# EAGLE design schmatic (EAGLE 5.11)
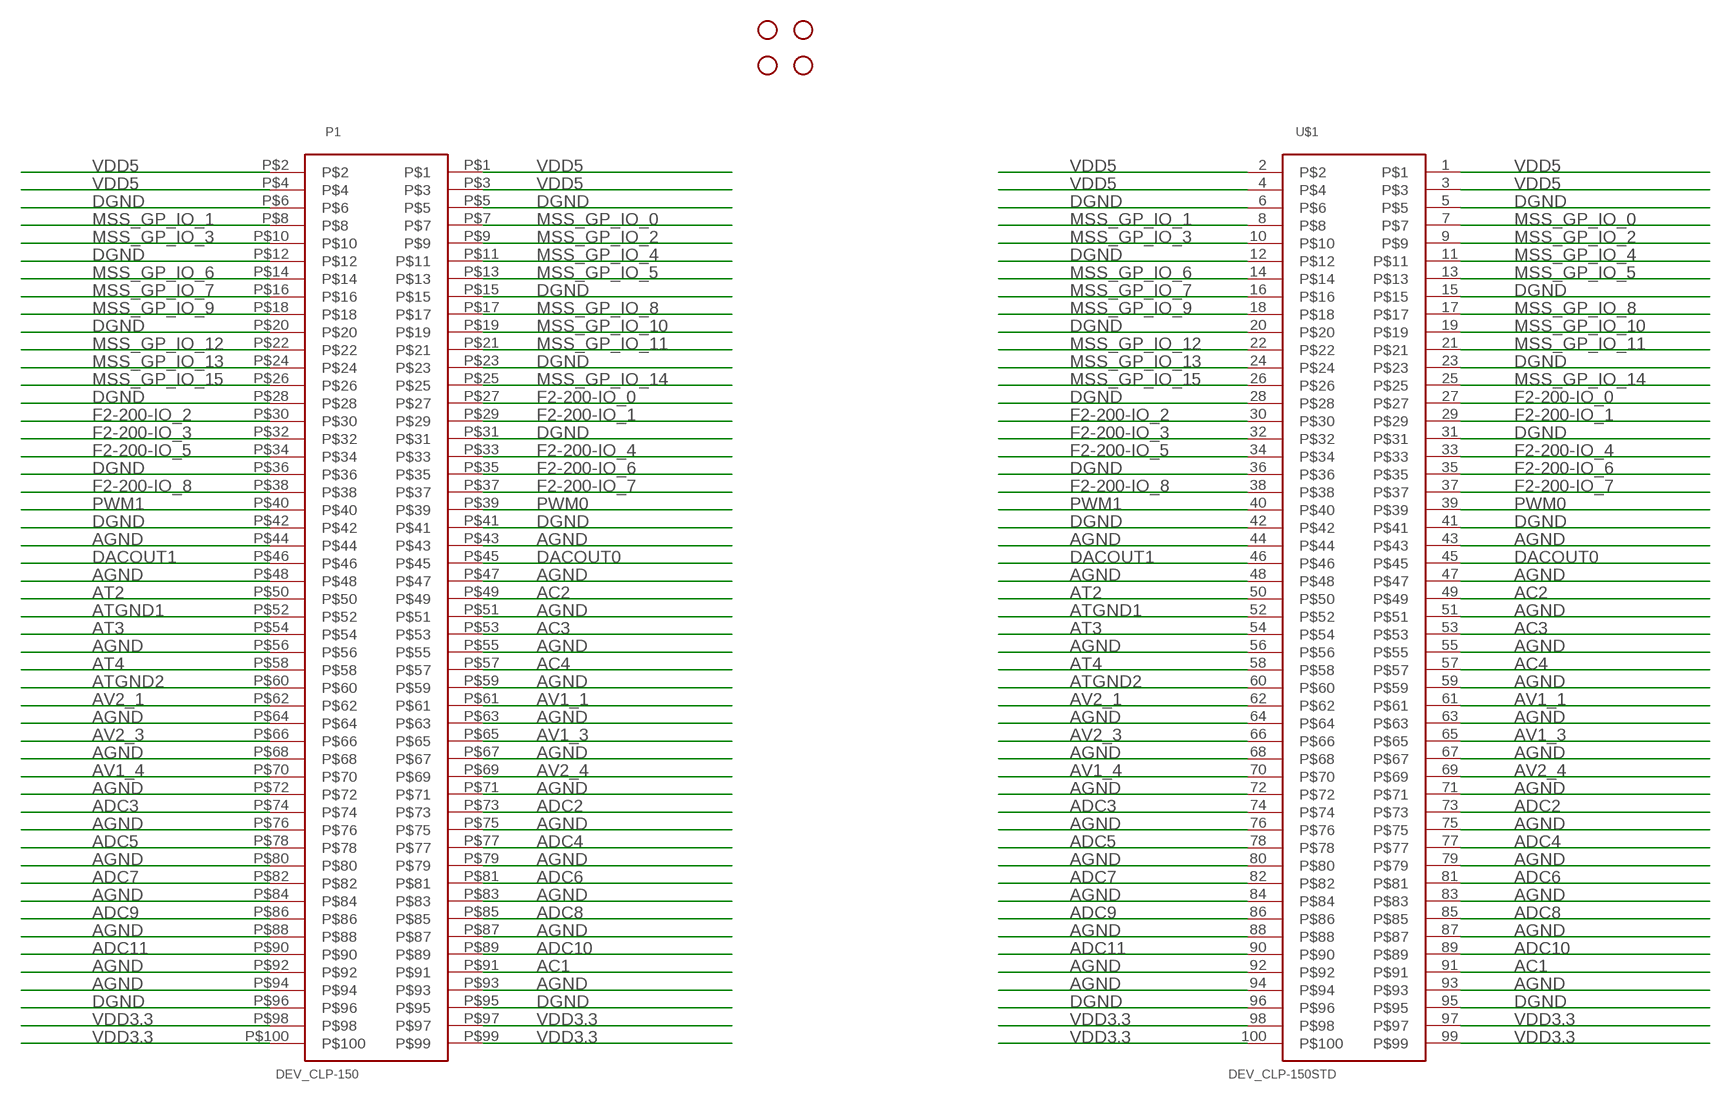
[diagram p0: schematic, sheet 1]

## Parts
JP1  STAND-OFF  [STAND-OFF]
JP2  STAND-OFF  [STAND-OFF]
JP3  STAND-OFF  [STAND-OFF]
JP4  STAND-OFF  [STAND-OFF]
P1  DEV_CLP-150  [CLP-150]
U$1  DEV_CLP-150STD  [100PIN_HEADER]

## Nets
AC1: P1.P$91 U$1.91
AC2: P1.P$49 U$1.49
AC3: P1.P$53 U$1.53
AC4: P1.P$57 U$1.57
ADC2: P1.P$73 U$1.73
ADC3: P1.P$74 U$1.74
ADC4: P1.P$77 U$1.77
ADC5: P1.P$78 U$1.78
ADC6: P1.P$81 U$1.81
ADC7: P1.P$82 U$1.82
ADC8: P1.P$85 U$1.85
ADC9: P1.P$86 U$1.86
ADC10: P1.P$89 U$1.89
ADC11: P1.P$90 U$1.90
AGND: P1.P$43 P1.P$44 P1.P$47 P1.P$48 P1.P$51 P1.P$55 P1.P$56 P1.P$59 P1.P$63 P1.P$64 P1.P$67 P1.P$68 P1.P$71 P1.P$72 P1.P$75 P1.P$76 P1.P$79 P1.P$80 P1.P$83 P1.P$84 P1.P$87 P1.P$88 P1.P$92 P1.P$93 P1.P$94 U$1.43 U$1.44 U$1.47 U$1.48 U$1.51 U$1.55 U$1.56 U$1.59 U$1.63 U$1.64 U$1.67 U$1.68 U$1.71 U$1.72 U$1.75 U$1.76 U$1.79 U$1.80 U$1.83 U$1.84 U$1.87 U$1.88 U$1.92 U$1.93 U$1.94
AT2: P1.P$50 U$1.50
AT3: P1.P$54 U$1.54
AT4: P1.P$58 U$1.58
ATGND1: P1.P$52 U$1.52
ATGND2: P1.P$60 U$1.60
AV1_1: P1.P$61 U$1.61
AV1_3: P1.P$65 U$1.65
AV1_4: P1.P$70 U$1.70
AV2_1: P1.P$62 U$1.62
AV2_3: P1.P$66 U$1.66
AV2_4: P1.P$69 U$1.69
DACOUT0: P1.P$45 U$1.45
DACOUT1: P1.P$46 U$1.46
DGND: P1.P$5 P1.P$6 P1.P$12 P1.P$15 P1.P$20 P1.P$23 P1.P$28 P1.P$31 P1.P$36 P1.P$41 P1.P$42 P1.P$95 P1.P$96 U$1.5 U$1.6 U$1.12 U$1.15 U$1.20 U$1.23 U$1.28 U$1.31 U$1.36 U$1.41 U$1.42 U$1.95 U$1.96
F2-200-IO_0: P1.P$27 U$1.27
F2-200-IO_1: P1.P$29 U$1.29
F2-200-IO_2: P1.P$30 U$1.30
F2-200-IO_3: P1.P$32 U$1.32
F2-200-IO_4: P1.P$33 U$1.33
F2-200-IO_5: P1.P$34 U$1.34
F2-200-IO_6: P1.P$35 U$1.35
F2-200-IO_7: P1.P$37 U$1.37
F2-200-IO_8: P1.P$38 U$1.38
MSS_GP_IO_0: P1.P$7 U$1.7
MSS_GP_IO_1: P1.P$8 U$1.8
MSS_GP_IO_2: P1.P$9 U$1.9
MSS_GP_IO_3: P1.P$10 U$1.10
MSS_GP_IO_4: P1.P$11 U$1.11
MSS_GP_IO_5: P1.P$13 U$1.13
MSS_GP_IO_6: P1.P$14 U$1.14
MSS_GP_IO_7: P1.P$16 U$1.16
MSS_GP_IO_8: P1.P$17 U$1.17
MSS_GP_IO_9: P1.P$18 U$1.18
MSS_GP_IO_10: P1.P$19 U$1.19
MSS_GP_IO_11: P1.P$21 U$1.21
MSS_GP_IO_12: P1.P$22 U$1.22
MSS_GP_IO_13: P1.P$24 U$1.24
MSS_GP_IO_14: P1.P$25 U$1.25
MSS_GP_IO_15: P1.P$26 U$1.26
PWM0: P1.P$39 U$1.39
PWM1: P1.P$40 U$1.40
VDD3.3: P1.P$97 P1.P$98 P1.P$99 P1.P$100 U$1.97 U$1.98 U$1.99 U$1.100
VDD5: P1.P$1 P1.P$2 P1.P$3 P1.P$4 U$1.1 U$1.2 U$1.3 U$1.4

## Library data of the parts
JP1-JP4 = SparkFun:STAND-OFF: Stand Off
P1 = EECS370:DEV_CLP-150
U$1 = sam:DEV_CLP-150

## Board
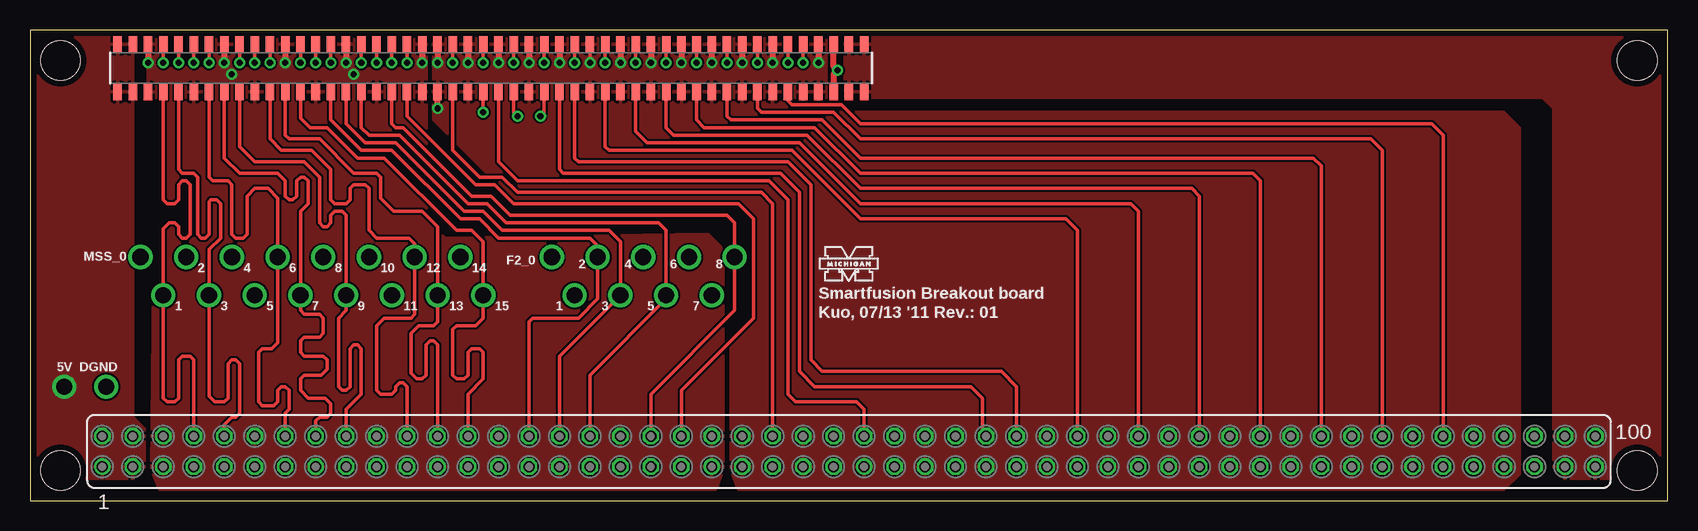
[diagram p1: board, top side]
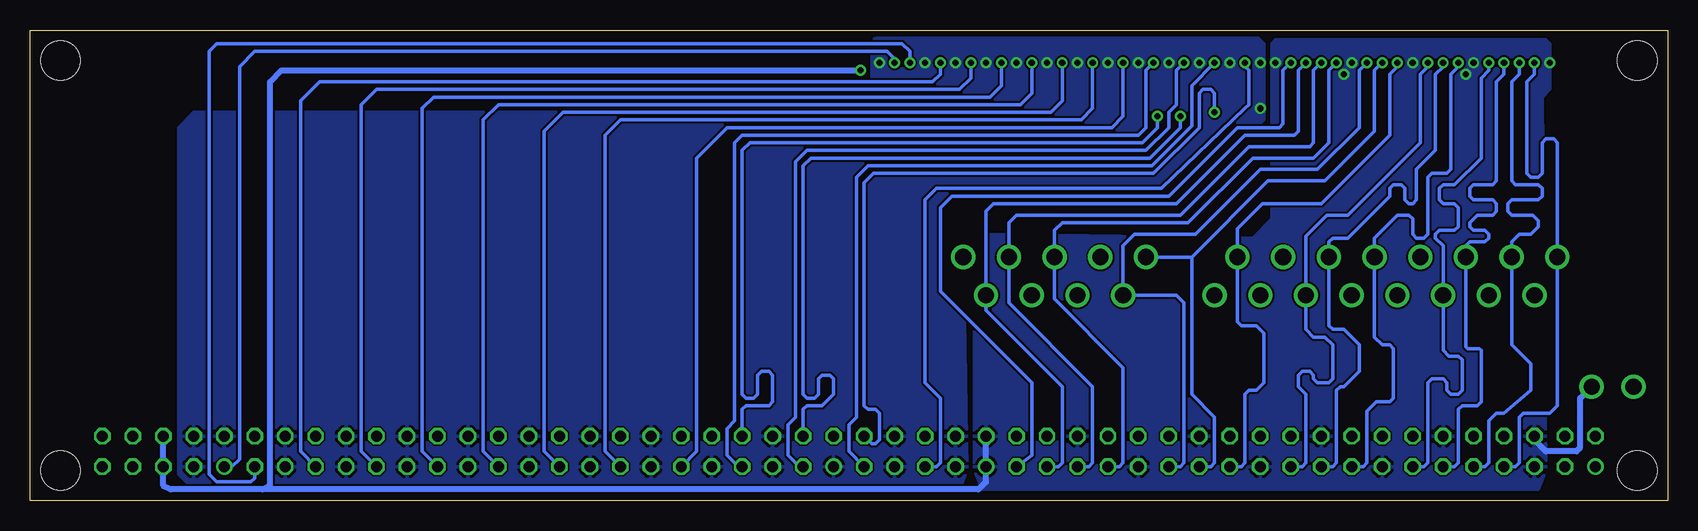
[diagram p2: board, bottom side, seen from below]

Size 136.53 x 39.24 mm. Coordinates in mm from the lower left corner, seen from the top.
Outline: 0,0 136.53,0 136.53,39.24 0,39.24 0,0
Copper layers (1*16): Top 0.0178mm / dielectric 1.4986mm / Bottom 0.0178mm
Design rules "SSC-EAGLE-2Lyr_v1.0.0.3": minimum track width 6mil, minimum drill 14mil, track to track 6mil, track to pad 6mil, pad to pad 6mil, via to via 6mil, smd to smd 6mil, copper to edge 20mil, drill to drill 16mil, minimum pad ring 8mil, minimum via ring 8mil, stop-mask expansion 3mil, vias tented up to drill 0mil, thermal gap 10mil

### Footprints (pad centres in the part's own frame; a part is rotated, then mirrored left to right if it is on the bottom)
STAND-OFF = hole 3.302: 0,0
CLP-150 = smd 0.711 x 1.35: P$1 -31.115,1.99; P$2 -31.115,-1.99; P$3 -29.845,1.99; P$4 -29.845,-1.99; P$5 -28.575,1.99; P$6 -28.575,-1.99; P$7 -27.305,1.99; P$8 -27.305,-1.99; P$9 -26.035,1.99; P$10 -26.035,-1.99; P$11 -24.765,1.99; P$12 -24.765,-1.99; P$13 -23.495,1.99; P$14 -23.495,-1.99; P$15 -22.225,1.99; P$16 -22.225,-1.99; P$17 -20.955,1.99; P$18 -20.955,-1.99; P$19 -19.685,1.99; P$20 -19.685,-1.99; P$21 -18.415,1.99; P$22 -18.415,-1.99; P$23 -17.145,1.99; P$24 -17.145,-1.99; P$25 -15.875,1.99; P$26 -15.875,-1.99; P$27 -14.605,1.99; P$28 -14.605,-1.99; P$29 -13.335,1.99; P$30 -13.335,-1.99; P$31 -12.065,1.99; P$32 -12.065,-1.99; P$33 -10.795,1.99; P$34 -10.795,-1.99; P$35 -9.525,1.99; P$36 -9.525,-1.99; P$37 -8.255,1.99; P$38 -8.255,-1.99; P$39 -6.985,1.99; P$40 -6.985,-1.99; P$41 -5.715,1.99; P$42 -5.715,-1.99; P$43 -4.445,1.99; P$44 -4.445,-1.99; P$45 -3.175,1.99; P$46 -3.175,-1.99; P$47 -1.905,1.99; P$48 -1.905,-1.99; P$49 -0.635,1.99; P$50 -0.635,-1.99; P$51 0.635,1.99; P$52 0.635,-1.99; P$53 1.905,1.99; P$54 1.905,-1.99; P$55 3.175,1.99; P$56 3.175,-1.99; P$57 4.445,1.99; P$58 4.445,-1.99; P$59 5.715,1.99; P$60 5.715,-1.99; P$61 6.985,1.99; P$62 6.985,-1.99; P$63 8.255,1.99; P$64 8.255,-1.99; P$65 9.525,1.99; P$66 9.525,-1.99; P$67 10.795,1.99; P$68 10.795,-1.99; P$69 12.065,1.99; P$70 12.065,-1.99; P$71 13.335,1.99; P$72 13.335,-1.99; P$73 14.605,1.99; P$74 14.605,-1.99; P$75 15.875,1.99; P$76 15.875,-1.99; P$77 17.145,1.99; P$78 17.145,-1.99; P$79 18.415,1.99; P$80 18.415,-1.99; P$81 19.685,1.99; P$82 19.685,-1.99; P$83 20.955,1.99; P$84 20.955,-1.99; P$85 22.225,1.99; P$86 22.225,-1.99; P$87 23.495,1.99; P$88 23.495,-1.99; P$89 24.765,1.99; P$90 24.765,-1.99; P$91 26.035,1.99; P$92 26.035,-1.99; P$93 27.305,1.99; P$94 27.305,-1.99; P$95 28.575,1.99; P$96 28.575,-1.99; P$97 29.845,1.99; P$98 29.845,-1.99; P$99 31.115,1.99; P$100 31.115,-1.99
100PIN_HEADER = drill 0.914 round: 1 -62.23,-1.27; 41 -11.43,-1.27; 51 1.27,-1.27; 91 52.07,-1.27 | drill 0.914 octagon: 2 -62.23,1.27; 3 -59.69,-1.27; 4 -59.69,1.27; 5 -57.15,-1.27; 6 -57.15,1.27; 7 -54.61,-1.27; 8 -54.61,1.27; 9 -52.07,-1.27; 10 -52.07,1.27; 11 -49.53,-1.27; 12 -49.53,1.27; 13 -46.99,-1.27; 14 -46.99,1.27; 15 -44.45,-1.27; 16 -44.45,1.27; 17 -41.91,-1.27; 18 -41.91,1.27; 19 -39.37,-1.27; 20 -39.37,1.27; 21 -36.83,-1.27; 22 -36.83,1.27; 23 -34.29,-1.27; 24 -34.29,1.27; 25 -31.75,-1.27; 26 -31.75,1.27; 27 -29.21,-1.27; 28 -29.21,1.27; 29 -26.67,-1.27; 30 -26.67,1.27; 31 -24.13,-1.27; 32 -24.13,1.27; 33 -21.59,-1.27; 34 -21.59,1.27; 35 -19.05,-1.27; 36 -19.05,1.27; 37 -16.51,-1.27; 38 -16.51,1.27; 39 -13.97,-1.27; 40 -13.97,1.27; 42 -11.43,1.27; 43 -8.89,-1.27; 44 -8.89,1.27; 45 -6.35,-1.27; 46 -6.35,1.27; 47 -3.81,-1.27; 48 -3.81,1.27; 49 -1.27,-1.27; 50 -1.27,1.27; 52 1.27,1.27; 53 3.81,-1.27; 54 3.81,1.27; 55 6.35,-1.27; 56 6.35,1.27; 57 8.89,-1.27; 58 8.89,1.27; 59 11.43,-1.27; 60 11.43,1.27; 61 13.97,-1.27; 62 13.97,1.27; 63 16.51,-1.27; 64 16.51,1.27; 65 19.05,-1.27; 66 19.05,1.27; 67 21.59,-1.27; 68 21.59,1.27; 69 24.13,-1.27; 70 24.13,1.27; 71 26.67,-1.27; 72 26.67,1.27; 73 29.21,-1.27; 74 29.21,1.27; 75 31.75,-1.27; 76 31.75,1.27; 77 34.29,-1.27; 78 34.29,1.27; 79 36.83,-1.27; 80 36.83,1.27; 81 39.37,-1.27; 82 39.37,1.27; 83 41.91,-1.27; 84 41.91,1.27; 85 44.45,-1.27; 86 44.45,1.27; 87 46.99,-1.27; 88 46.99,1.27; 89 49.53,-1.27; 90 49.53,1.27; 92 52.07,1.27; 93 54.61,-1.27; 94 54.61,1.27; 95 57.15,-1.27; 96 57.15,1.27; 97 59.69,-1.27; 98 59.69,1.27; 99 62.23,-1.27; 100 62.23,1.27

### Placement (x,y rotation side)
JP1  2.54,36.7 90 top
JP2  2.54,2.54 0 top
JP3  133.99,36.7 0 top
JP4  133.99,2.54 0 top
P1  38.42,36.07 0 top
U$1  68.26,4.13 0 top
U$2  [UMICH]  65.72,18.1 0 top

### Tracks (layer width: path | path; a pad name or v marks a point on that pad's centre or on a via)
AC1  (via drill 0.51)
  Top 0.305: P1.P$91 v64.45,36.51
  Bottom 0.305: v64.45,36.51 64.45,36.83 65.09,37.47 117.79,37.47 119.06,36.2 119.06,3.49 119.7,2.86 U$1.91
AC2  (via drill 0.51)
  Top 0.305: v37.78,36.51 P1.P$49
  Bottom 0.305: v37.78,36.51 39.69,34.61 39.69,31.27 43.02,27.94 66.67,27.94 67.63,26.99 67.63,6.99 68.26,6.35 68.26,4.13 U$1.49
AC3  (via drill 0.51)
  Top 0.305: v40.32,36.51 P1.P$53
  Bottom 0.305: v40.32,36.51 40.96,35.88 40.96,33.02 41.59,32.38 41.59,31.11 43.5,29.21 71.75,29.21 72.71,28.26 72.71,6.99 73.34,6.35 73.34,3.81 72.39,2.86 U$1.53
AC4  (via drill 0.51)
  Top 0.305: v42.86,36.51 P1.P$57
  Bottom 0.305: v42.86,36.51 43.5,35.88 43.5,31.11 44.13,30.48 77.15,30.48 77.79,29.84 77.79,6.67 78.42,6.03 78.42,3.81 77.47,2.86 U$1.57
ADC2  (via drill 0.51)
  Top 0.305: v53.02,36.51 P1.P$73
  Bottom 0.305: U$1.73 98.74,4.13 98.74,31.75 97.47,33.02 53.98,33.02 53.02,33.97 v53.02,36.51
ADC3
  Top 0.305: P1.P$74 53.02,31.11 53.66,30.48 64.77,30.48 69.22,26.04 96.84,26.04 97.47,25.4 U$1.74
ADC4  (via drill 0.51)
  Top 0.305: v55.56,36.51 P1.P$77
  Bottom 0.305: U$1.77 103.82,4.13 103.82,32.7 102.87,33.66 56.52,33.66 55.56,34.61 v55.56,36.51
ADC5
  Top 0.305: P1.P$78 55.56,31.75 56.2,31.11 65.41,31.11 69.22,27.3 101.92,27.3 102.55,26.67 U$1.78
ADC6  (via drill 0.51)
  Top 0.305: v58.1,36.51 P1.P$81
  Bottom 0.305: U$1.81 108.9,4.13 108.9,33.02 107.63,34.29 59.05,34.29 58.1,35.24 v58.1,36.51
ADC7
  Top 0.305: P1.P$82 58.1,32.07 58.42,31.75 66.04,31.75 69.22,28.57 107,28.57 107.63,27.94 U$1.82
ADC8  (via drill 0.51)
  Top 0.305: P1.P$85 v60.64,36.51
  Bottom 0.305: v60.64,36.51 60.64,35.56 61.28,34.92 112.39,34.92 113.98,33.34 113.98,4.13 U$1.85
ADC9
  Top 0.305: P1.P$86 60.64,32.7 60.96,32.38 66.99,32.38 69.22,30.16 111.76,30.16 112.71,29.21 U$1.86
ADC10  (via drill 0.51)
  Top 0.305: P1.P$89 v63.18,36.51
  Bottom 0.305: v63.18,36.51 63.18,37.47 63.82,38.1 120.97,38.1 121.6,37.47 121.6,2.22 120.97,1.59 118.11,1.59 117.79,1.91 U$1.89
ADC11
  Top 0.305: P1.P$90 63.18,33.34 63.5,33.02 67.63,33.02 69.22,31.43 116.84,31.43 117.79,30.48 U$1.90
AGND  (via drill 0.51)
  Top 0.305: P1.P$63 v46.67,36.51
  Top 0.508: P1.P$47 v36.51,36.51 | P1.P$51 v39.05,36.51 | P1.P$55 v41.59,36.51 | P1.P$59 v44.13,36.51 | P1.P$67 v49.21,36.51 | P1.P$71 v51.75,36.51 | P1.P$75 v54.29,36.51 | P1.P$79 v56.83,36.51 | P1.P$83 v59.37,36.51 | P1.P$87 v61.91,36.51 | P1.P$93 v65.72,36.51 | P1.P$43 v33.97,36.51 | v33.97,32.7 P1.P$44
  pour Bottom: 33.66,38.1 34.29,38.73 65.41,38.73 66.36,38.42 66.36,32.38 122.87,32.38 124.14,31.11 124.14,2.22 122.87,0.95 59.05,0.95 58.42,2.54 58.74,22.86 57.78,23.81 41.59,23.81 33.66,31.75
  pour Top: 33.66,38.1 34.29,38.73 65.41,38.73 66.36,38.42 66.36,32.38 122.87,32.38 124.14,31.11 124.14,2.22 122.87,0.95 59.05,0.95 58.42,2.54 58.42,23.18 57.78,23.81 41.59,23.81 33.66,31.75
AT2  (via drill 0.51)
  Top 0.305: v37.78,32.38 P1.P$50
  Bottom 0.305: v37.78,32.38 37.78,33.97 38.1,34.29 38.73,34.29 39.05,33.97 39.05,31.11 42.86,27.3 66.2,27.3 66.99,26.51 66.99,7.94 66.67,7.62 66.04,7.62 65.72,7.3 65.72,5.08 66.04,4.76 66.36,4.76 U$1.50
AT3  (via drill 0.51)
  Top 0.305: P1.P$54 40.32,32.38 v40.64,32.07
  Bottom 0.305: v40.64,32.07 40.64,31.11 43.18,28.57 71.44,28.57 72.07,27.94 72.07,8.89 71.75,8.57 71.12,8.57 70.8,8.89 70.8,10.16 70.48,10.48 69.85,10.48 69.53,10.16 69.53,8.89 70.48,7.94 71.75,7.94 72.07,7.62 U$1.54
AT4  (via drill 0.51)
  Top 0.305: P1.P$58 42.86,32.38 v42.55,32.07
  Bottom 0.305: v42.55,32.07 42.55,31.11 43.81,29.84 76.52,29.84 77.15,29.21 77.15,8.89 76.83,8.57 76.2,8.57 75.88,8.89 75.88,10.48 75.56,10.79 74.93,10.79 74.61,10.48 74.61,8.26 74.93,7.94 76.83,7.94 77.15,7.62 U$1.58
ATGND1
  Top 0.305: P1.P$52 39.05,28.26 40.64,26.67 61.59,26.67 63.18,25.08 63.18,8.89 63.82,8.26 68.9,8.26 69.53,7.62 U$1.52
ATGND2
  Top 0.305: P1.P$60 44.13,27.62 44.45,27.3 62.55,27.3 64.14,25.72 64.14,10.79 65.41,9.53 78.42,9.53 79.38,8.57 79.38,5.71 U$1.60
AV1_1  (via drill 0.51)
  Top 0.305: v45.4,36.51 P1.P$61
  Bottom 0.305: U$1.61 80.96,4.13 80.96,28.57 78.42,31.11 46.35,31.11 45.4,32.07 v45.4,36.51
AV1_3  (via drill 0.51)
  Top 0.305: v47.94,36.51 P1.P$65
  Bottom 0.305: U$1.65 88.58,4.13 88.58,30.48 87.31,31.75 48.9,31.75 47.94,32.7 v47.94,36.51
AV1_4
  Top 0.305: P1.P$70 50.48,30.8 51.44,29.84 64.14,29.84 69.22,24.77 91.76,24.77 92.39,24.13 U$1.70
AV2_1
  Top 0.305: P1.P$62 45.4,28.57 45.72,28.26 63.18,28.26 65.09,26.35 65.09,11.75 66.04,10.79 80.96,10.79 82.23,9.53 U$1.62
AV2_3
  Top 0.305: P1.P$66 47.94,29.53 48.26,29.21 63.5,29.21 69.22,23.5 86.36,23.5 87.31,22.54 U$1.66
AV2_4  (via drill 0.51)
  Top 0.305: v50.48,36.51 P1.P$69
  Bottom 0.305: U$1.69 93.66,4.13 93.66,30.8 92.08,32.38 51.44,32.38 50.48,33.34 v50.48,36.51
DACOUT0  (via drill 0.51)
  Top 0.305: v35.24,36.51 P1.P$45
  Bottom 0.305: U$1.45 60.96,2.86 60.64,3.17 60.64,8.57 61.91,9.84 61.91,25.08 60.96,26.04 42.23,26.04 35.24,32.7 34.92,33.02 34.92,35.88 35.24,36.2 v35.24,36.51
DACOUT1
  Top 0.305: P1.P$46 35.24,29.21 37.47,26.99 39.37,26.99 40.64,25.72 60.96,25.72 61.91,24.77 U$1.46
DGND  (via drill 0.51, 1.35)
  Top 0.508: P1.P$15 v16.19,36.51 | P1.P$23 v21.27,36.51 | P1.P$31 v26.35,36.51 | P1.P$41 v32.7,36.51 | P1.P$5 v9.84,36.51 | P1.P$96 66.99,35.56 v67.31,35.88 66.99,36.2 P1.P$95
  Bottom 0.508: 117.16,0.95 116.52,1.27 116.52,34.92 115.57,35.88 v67.31,35.88 | 117.16,0.95 124.78,0.95 125.41,1.27 U$1.95 U$1.96 | U$1.42 56.83,1.59 57.47,0.95 117.16,0.95 | U$1.6 11.11,5.08 10.16,4.13 7.62,4.13 7.3,4.45 7.3,8.57 v6.35,9.53
  other vias: 16.83,35.56 26.99,35.56
  pour Bottom: 9.84,38.1 9.84,34.29 10.48,33.66 10.16,2.54 10.79,0.95 57.15,0.95 57.78,2.54 57.78,20.95 56.52,22.23 34.61,21.91 33.02,23.5 33.02,38.1 32.7,38.42 10.16,38.42
  pour Top: 9.84,38.1 9.84,34.29 10.48,33.66 10.16,2.54 10.79,0.95 57.15,0.95 57.78,2.54 57.78,20.95 56.52,22.23 34.61,21.91 33.02,23.5 33.02,38.1 32.7,38.42 10.16,38.42
F2-200-IO_0  (via drill 0.51, 1.35)
  Top 0.305: v23.81,36.51 P1.P$27
  Bottom 0.305: v23.81,36.51 24.45,35.88 24.45,30.8 28.57,26.67 33.34,26.67 39.69,20.32 | 39.69,20.32 v43.5,20.32 | U$1.27 38.1,2.86 37.78,3.17 37.78,6.99 39.69,8.89 39.69,20.32
F2-200-IO_1  (via drill 0.51, 1.35)
  Top 0.305: v25.08,36.51 P1.P$29
  Bottom 0.305: v25.08,36.51 25.72,35.88 25.72,31.11 29.21,27.62 33.97,27.62 39.37,22.23 44.45,22.23 45.4,21.27 v45.4,17.14 40.96,17.14 40.32,16.51 40.32,3.17 40.64,2.86 U$1.29
F2-200-IO_2  (via drill 1.35)
  Top 0.305: P1.P$30 25.08,31.75 27.62,29.21 30.16,29.21 35.88,23.5 37.47,23.5 39.05,21.91 46.67,21.91 47.31,21.27 v47.31,20.32 47.31,16.83 45.72,15.24 41.91,15.24 41.59,14.92 U$1.30
F2-200-IO_3  (via drill 1.35)
  Top 0.305: P1.P$32 26.35,31.43 27.94,29.84 30.48,29.84 36.2,24.13 37.78,24.13 39.37,22.54 48.26,22.54 49.21,21.59 v49.21,17.14 44.13,12.06 U$1.32
F2-200-IO_4  (via drill 0.51, 1.35)
  Top 0.305: v27.62,36.51 P1.P$33
  Bottom 0.305: v27.62,36.51 28.26,35.88 28.26,29.84 29.53,28.57 34.61,28.57 40.01,23.18 50.48,23.18 51.12,22.54 v51.12,20.32 51.12,16.83 45.4,11.11 45.4,3.17 45.72,2.86 U$1.33
F2-200-IO_5  (via drill 1.35)
  Top 0.305: P1.P$34 27.62,31.11 28.26,30.48 30.8,30.48 36.51,24.77 38.1,24.77 39.69,23.18 52.39,23.18 53.02,22.54 v53.02,17.14 53.02,16.83 46.67,10.48 U$1.34
F2-200-IO_6  (via drill 0.51, 1.35)
  Top 0.305: v28.89,36.51 P1.P$35
  Bottom 0.305: v28.89,36.51 29.53,35.88 29.53,29.84 29.84,29.53 34.92,29.53 40.64,23.81 54.29,23.81 54.93,23.18 v54.93,20.32 54.93,16.51 47.94,9.53 47.94,3.17 48.26,2.86 U$1.35
F2-200-IO_7  (via drill 0.51, 1.35)
  Top 0.305: v30.16,36.51 P1.P$37
  Bottom 0.305: v30.16,36.51 30.8,35.88 30.8,30.8 31.11,30.48 35.24,30.48 40.96,24.77 56.2,24.77 56.83,24.13 v56.83,17.14 56.83,15.88 50.48,9.53 50.48,3.17 50.8,2.86 U$1.37
F2-200-IO_8  (via drill 1.35)
  Top 0.305: P1.P$38 30.16,31.43 30.48,31.11 31.11,31.11 36.83,25.4 38.42,25.4 40.01,23.81 58.1,23.81 58.74,23.18 v58.74,20.32 58.74,15.88 51.75,8.89 U$1.38
MSS_GP_IO_0  (via drill 0.51, 1.35)
  Top 0.305: v11.11,36.51 P1.P$7
  Bottom 0.305: v11.11,36.51 11.11,35.56 11.75,34.92 11.75,27.3 11.43,26.99 10.79,26.99 10.48,27.3 10.48,29.84 10.16,30.16 9.53,30.16 9.21,29.84 v9.21,20.32 9.21,7.94 9.84,7.3 12.06,7.3 12.38,6.99 12.38,3.17 12.7,2.86 U$1.7
MSS_GP_IO_1  (via drill 1.35)
  Top 0.305: P1.P$8 11.11,25.08 11.43,24.77 12.06,24.77 12.38,25.08 12.38,26.35 12.7,26.67 13.02,26.67 13.34,26.35 13.34,22.23 13.02,21.91 12.7,21.91 12.38,22.23 12.38,22.86 12.06,23.18 11.59,23.18 11.11,22.7 v11.11,17.14 11.11,8.57 11.43,8.26 12.06,8.26 12.38,8.57 12.38,11.75 12.7,12.06 13.34,12.06 13.65,11.75 U$1.8
MSS_GP_IO_2  (via drill 0.51, 1.35)
  Top 0.305: v12.38,36.51 P1.P$9
  Bottom 0.305: v12.38,36.51 12.38,35.56 13.02,34.92 13.02,26.67 12.7,26.35 10.79,26.35 10.48,26.04 10.48,25.4 10.79,25.08 13.02,25.08 13.34,24.77 13.34,24.13 13.02,23.81 11.27,23.81 10.79,23.34 10.79,22.86 11.43,22.23 12.38,22.23 13.02,21.59 v13.02,20.32 13.02,13.02 11.43,11.43 11.43,9.21 13.65,7.3 14.29,7.3 14.92,6.67 14.92,3.17 15.24,2.86 U$1.9
MSS_GP_IO_3  (via drill 1.35)
  Top 0.305: P1.P$10 12.38,27.62 12.7,27.3 13.65,27.3 13.97,26.99 13.97,22.23 14.29,21.91 14.61,21.91 14.92,22.23 14.92,24.92 15.08,25.08 15.56,25.08 15.88,24.77 15.88,21.91 14.92,20.95 v14.92,17.14 14.92,8.73 15.4,8.26 16.19,8.26 16.51,8.57 16.51,11.43 16.83,11.75 17.14,11.75 17.46,11.43 17.46,7.3 17.14,6.99 16.83,6.99 16.19,6.35 U$1.10
MSS_GP_IO_4  (via drill 0.51, 1.35)
  Top 0.305: v13.65,36.51 P1.P$11
  Bottom 0.305: v13.65,36.51 13.65,35.56 14.29,34.92 14.29,26.67 14.61,26.35 16.19,26.35 16.51,26.04 16.51,25.4 16.19,25.08 14.61,25.08 14.29,24.77 14.29,24.13 14.61,23.81 15.88,23.81 16.51,23.18 16.51,22.86 16.19,22.54 15.24,22.54 14.92,22.23 14.92,21.91 15.24,21.59 16.51,21.59 16.83,21.27 v16.83,20.32 16.83,12.86 16.67,12.7 15.72,12.7 15.56,12.54 15.56,8.26 15.88,7.94 17.14,7.94 17.46,7.62 17.46,3.17 17.78,2.86 U$1.11
MSS_GP_IO_5  (via drill 0.51, 1.35)
  Top 0.305: v14.92,36.51 P1.P$13
  Bottom 0.305: v14.92,36.51 14.92,35.88 15.56,35.24 15.56,28.57 17.78,26.35 18.73,26.35 19.05,26.04 19.05,25.08 18.73,24.77 17.78,24.77 17.46,24.45 17.46,22.86 17.78,22.54 19.05,22.54 19.37,22.23 19.37,21.91 18.73,21.27 v18.73,17.14 18.73,12.54 18.26,12.06 17.46,12.06 17.14,11.75 17.14,9.21 17.46,8.89 18.1,8.89 18.41,9.21 18.41,9.84 18.73,10.16 19.68,10.16 20,9.84 20,3.17 20.32,2.86 U$1.13
MSS_GP_IO_6  (via drill 1.35)
  Top 0.305: P1.P$14 14.92,26.99 15.24,26.67 16.51,26.67 16.83,26.35 16.83,22.23 17.14,21.91 17.78,21.91 18.1,22.23 18.1,25.4 18.73,26.04 19.84,26.04 20.64,25.24 v20.64,20.32 20.64,13.18 20.16,12.7 19.37,12.7 19.05,12.38 19.05,8.26 19.37,7.94 20.32,7.94 20.64,8.26 20.64,9.21 20.95,9.53 21.27,9.53 21.59,9.21 21.59,7.62 21.27,7.3 U$1.14
MSS_GP_IO_7  (via drill 1.35)
  Top 0.305: P1.P$16 16.19,28.57 17.46,27.3 20.64,27.3 21.27,26.67 21.27,25.4 21.59,25.08 21.91,25.08 22.23,25.4 22.23,26.67 22.54,26.99 22.86,26.99 23.18,26.67 23.18,24.77 22.54,24.13 v22.54,17.14 22.54,15.88 22.86,15.56 24.13,15.56 24.45,15.24 24.45,13.97 24.13,13.65 22.86,13.65 22.54,13.34 22.54,12.38 22.86,12.06 24.45,12.06 24.77,11.75 24.77,10.95 24.29,10.48 22.86,10.48 22.54,10.16 22.54,9.21 23.18,8.57 24.61,8.57 25.08,8.1 25.08,7.3 24.77,6.99 24.13,6.99 23.81,6.67 U$1.16
MSS_GP_IO_8  (via drill 0.51, 1.35)
  Top 0.305: v17.46,36.51 P1.P$17
  Bottom 0.305: v17.46,36.51 17.46,36.2 18.1,35.56 18.1,27.62 18.41,27.3 19.68,27.3 20,26.99 20,22.23 20.32,21.91 20.95,21.91 21.27,22.23 21.27,23.5 21.59,23.81 22.54,23.81 24.45,21.91 v24.45,20.32 24.45,13.65 23.81,13.02 23.18,13.02 22.86,12.7 22.86,8.57 23.18,8.26 24.29,8.26 25.08,7.46 25.08,3.17 25.4,2.86 U$1.17
MSS_GP_IO_9  (via drill 1.35)
  Top 0.305: P1.P$18 17.46,29.53 18.73,28.26 22.86,28.26 24.13,26.99 24.13,23.18 24.45,22.86 24.77,22.86 25.08,23.18 25.08,23.81 25.4,24.13 26.04,24.13 26.35,23.81 v26.35,17.14 26.35,15.88 25.72,15.24 25.72,9.53 26.04,9.21 26.35,9.21 26.67,9.53 26.67,12.7 26.99,13.02 27.3,13.02 27.62,12.7 27.62,8.89 26.35,7.62 U$1.18
MSS_GP_IO_10  (via drill 0.51, 1.35)
  Top 0.305: v18.73,36.51 P1.P$19
  Bottom 0.305: v18.73,36.51 18.73,36.2 19.37,35.56 19.37,29.21 20.95,27.62 20.95,25.08 21.27,24.77 21.59,24.77 21.91,25.08 21.91,26.04 22.23,26.35 22.86,26.35 23.18,26.04 23.18,25.4 26.67,21.91 27.94,21.91 28.26,21.59 v28.26,20.32 28.26,14.61 27.94,14.29 26.99,14.29 25.72,13.02 25.72,10.79 26.99,9.53 27.3,9.53 27.62,9.21 27.62,3.17 27.94,2.86 U$1.19
MSS_GP_IO_11  (via drill 0.51, 1.35)
  Top 0.305: v20,36.51 P1.P$21
  Bottom 0.305: v20,36.51 20,36.2 20.64,35.56 20.64,29.84 26.67,23.81 28.42,23.81 30.16,22.07 v30.16,17.14 30.16,14.29 29.53,13.65 28.57,13.65 27.94,13.02 27.94,10.16 28.26,9.84 29.21,9.84 29.53,10.16 29.53,10.48 29.84,10.79 30.48,10.79 30.8,10.48 30.8,9.53 30.16,8.89 30.16,3.17 30.48,2.86 U$1.21
MSS_GP_IO_12  (via drill 1.35)
  Top 0.305: P1.P$22 20,30.16 20.95,29.21 23.5,29.21 25.08,27.62 25.08,25.08 25.4,24.77 26.35,24.77 26.67,25.08 26.67,26.04 26.99,26.35 27.94,26.35 28.26,26.04 28.26,22.54 28.89,21.91 31.59,21.91 32.07,21.43 v32.07,20.32 32.07,15.56 31.75,15.24 29.53,15.24 28.89,14.61 28.89,9.21 29.21,8.89 30.16,8.89 30.48,9.21 30.48,9.53 30.8,9.84 31.11,9.84 31.43,9.53 U$1.22
MSS_GP_IO_13  (via drill 1.35)
  Top 0.305: P1.P$24 21.27,30.48 21.59,30.16 24.13,30.16 26.99,27.3 28.89,27.3 29.21,26.99 29.21,25.24 30.32,24.13 32.7,24.13 33.97,22.86 v33.97,17.14 33.97,14.92 33.66,14.61 32.38,14.61 31.75,13.97 31.75,10.64 32.23,10.16 32.7,10.16 33.02,10.48 33.02,13.02 33.34,13.34 33.66,13.34 33.97,13.02 U$1.24
MSS_GP_IO_14  (via drill 0.51, 1.35)
  Top 0.305: v22.54,36.51 P1.P$25
  Bottom 0.305: v22.54,36.51 22.54,36.2 23.18,35.56 23.18,30.48 28.89,24.77 33.81,24.77 35.88,22.7 v35.88,20.32 35.88,14.92 35.56,14.61 34.29,14.61 33.66,13.97 33.66,9.84 34.29,9.21 34.92,9.21 35.24,8.89 35.24,3.17 35.56,2.86 U$1.25
MSS_GP_IO_15  (via drill 1.35)
  Top 0.305: P1.P$26 22.54,31.91 23.34,31.11 24.77,31.11 27.3,28.57 29.53,28.57 35.56,22.54 36.83,22.54 37.78,21.59 v37.78,17.14 37.78,15.24 37.15,14.61 35.56,14.61 35.24,14.29 35.24,10.48 35.56,10.16 36.2,10.16 36.51,10.48 36.51,12.38 36.83,12.7 37.47,12.7 37.78,12.38 37.78,10.16 36.51,8.89 U$1.26
PWM0  (via drill 0.51)
  Top 0.305: v31.43,36.51 P1.P$39
  Bottom 0.305: U$1.39 53.02,3.81 53.02,9.84 60.64,17.46 60.64,24.45 59.69,25.4 41.59,25.4 35.88,31.11 32.38,31.11 32.07,31.43 32.07,35.88 v31.43,36.51
PWM1
  Top 0.305: P1.P$40 31.43,32.07 37.15,26.35 38.73,26.35 40.32,24.77 59.05,24.77 60.33,23.5 60.33,15.24 54.29,9.21 U$1.40
VDD3.3
  pour Top: 67.94,38.1 67.94,34.29 68.26,33.66 126.05,33.66 127,32.7 127,2.54 127.64,1.91 135.57,1.91 135.89,2.22 135.89,37.47 134.62,38.73 68.58,38.73
VDD5  (via drill 1.35)
  other vias: 2.86,9.53
  pour Top: 8.57,38.42 8.57,6.99 9.53,6.03 9.53,2.54 8.89,1.91 1.27,1.91 0.64,2.54 0.64,38.1 1.27,38.73 8.26,38.73

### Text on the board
tPlace: MSS_0 | F2_0 | 2 | 4 | 6 | 8 | 10 | 12 | 14 | 2 | 4 | 6 | 8 | Smartfusion Breakout board | 1 | 3 | 5 | 7 | 9 | 11 | 13 | 15 | 1 | 3 | 5 | 7 | Kuo, 07/13 '11 Rev.: 01 | 5V DGND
